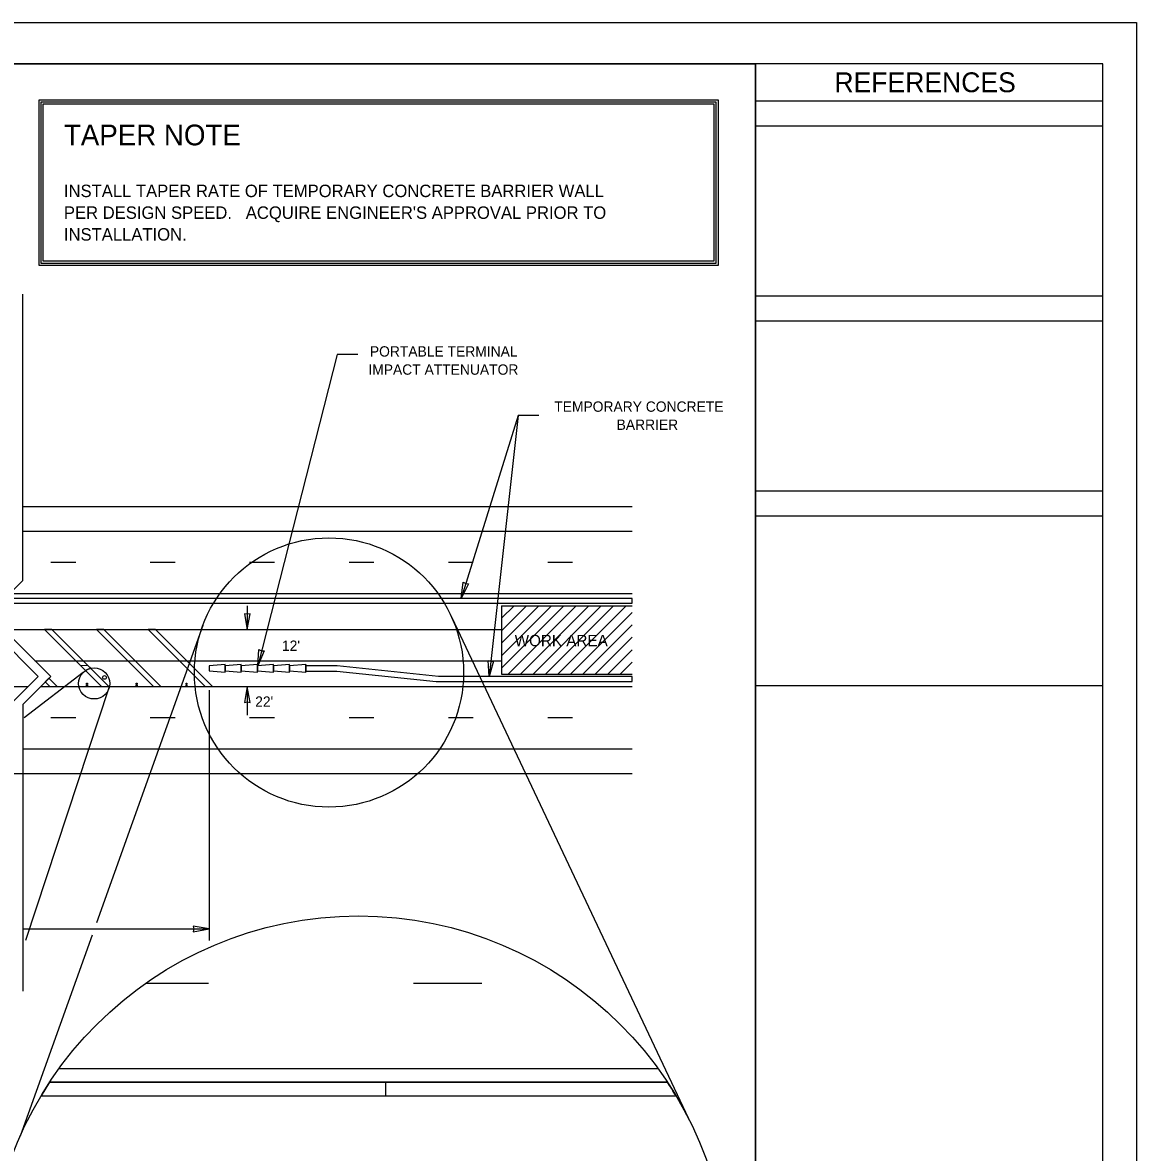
# Model space of a CAD drawing. Extents: x -2541 to -1265, y -5743 to -4928.
# Drawn here: x -1696.1 to -1265.8, y -5364.1 to -4927.7 of the extents above; entities that cross this region are included whole.
import ezdxf

# ---------------------------------------------------------------- set-up
doc = ezdxf.new("R2010")
doc.units = 0
for name, color, linetype in [('Level 42', 7, 'Continuous'), ('Level 45', 7, 'Continuous'), ('Level 46', 7, 'Continuous'), ('Level 47', 7, 'Continuous'), ('Level 48', 7, 'Continuous'), ('Level 49', 7, 'Continuous'), ('Level 50', 7, 'Continuous'), ('TR_WZ_TC_Edge Lines', 7, 'Continuous')]:
    doc.layers.add(name, color=color, linetype=linetype)

msp = doc.modelspace()

# ---------------------------------------------------------------- linework, layer by layer
at = {"layer": 'Level 42'}
for p, q in [((-1278.76, -4943.69), (-2472.96, -4943.66)), ((-1412.92, -5724.9), (-1412.92, -4943.73)), ((-1278.76, -5724.9), (-1278.76, -4943.69)), ((-1412.92, -4957.91), (-1278.91, -4957.91)), ((-1278.83, -4967.73), (-1412.92, -4967.73)), ((-1412.92, -5033.21), (-1278.91, -5033.21)), ((-1278.83, -5043.03), (-1412.92, -5043.03)), ((-1412.92, -5108.5), (-1278.91, -5108.5)), ((-1278.83, -5118.32), (-1412.92, -5118.32)), ((-1412.92, -5183.8), (-1278.76, -5183.8))]:
    msp.add_line(p, q, dxfattribs=at)
for points in [[(-2472.96, -4943.66), (-1412.92, -4943.66), (-1412.92, -5724.9), (-2472.96, -5724.9)], [(-1689.75, -4957.5), (-1427.42, -4957.5), (-1427.42, -5021.5), (-1689.75, -5021.5)], [(-1688.95, -4958.3), (-1428.22, -4958.3), (-1428.22, -5020.7), (-1688.95, -5020.7)], [(-1688.15, -4959.1), (-1429.02, -4959.1), (-1429.02, -5019.9), (-1688.15, -5019.9)]]:
    msp.add_lwpolyline(points, close=True, dxfattribs=at)
at = {"layer": 'Level 45'}
for p, q in [((-1701.04, -5148.16), (-1460.65, -5148.16)), ((-2451.65, -5184.16), (-1693.96, -5184.16)), ((-1689.15, -5184.16), (-1460.65, -5184.16)), ((-1671.38, -5183.2), (-1671.38, -5182.88)), ((-1671.38, -5182.88), (-1671.06, -5182.88)), ((-1671.06, -5183.2), (-1671.38, -5183.2)), ((-1671.38, -5183.84), (-1671.38, -5183.52)), ((-1671.38, -5183.52), (-1671.06, -5183.52)), ((-1671.06, -5183.84), (-1671.38, -5183.84)), ((-1671.06, -5182.88), (-1671.06, -5183.2)), ((-1671.06, -5183.52), (-1671.06, -5183.84)), ((-1652.18, -5183.2), (-1652.18, -5182.88)), ((-1652.18, -5182.88), (-1651.86, -5182.88)), ((-1651.86, -5183.2), (-1652.18, -5183.2)), ((-1652.18, -5183.84), (-1652.18, -5183.52)), ((-1652.18, -5183.52), (-1651.86, -5183.52)), ((-1651.86, -5183.84), (-1652.18, -5183.84)), ((-1651.86, -5182.88), (-1651.86, -5183.2)), ((-1651.86, -5183.52), (-1651.86, -5183.84)), ((-1632.98, -5183.2), (-1632.98, -5182.88)), ((-1632.98, -5182.88), (-1632.66, -5182.88)), ((-1632.66, -5183.2), (-1632.98, -5183.2)), ((-1632.98, -5183.84), (-1632.98, -5183.52)), ((-1632.98, -5183.52), (-1632.66, -5183.52)), ((-1632.66, -5183.84), (-1632.98, -5183.84)), ((-1632.66, -5182.88), (-1632.66, -5183.2)), ((-1632.66, -5183.52), (-1632.66, -5183.84)), ((-1682, -5331.68), (-1450.64, -5331.68))]:
    msp.add_line(p, q, dxfattribs=at)
at = {"layer": 'Level 46'}
for p, q in [((-1574.58, -5055.92), (-1605.29, -5176.11)), ((-1566.58, -5055.92), (-1574.58, -5055.92)), ((-1504.7, -5079.42), (-1526.67, -5150.08)), ((-1504.7, -5079.42), (-1515.86, -5180.32)), ((-1496.7, -5079.42), (-1504.7, -5079.42)), ((-1696.04, -5114.56), (-1460.65, -5114.56)), ((-1696.04, -5124.16), (-1460.65, -5124.16)), ((-1685.2, -5136.16), (-1675.6, -5136.16)), ((-1646.8, -5136.16), (-1637.2, -5136.16)), ((-1608.4, -5136.16), (-1598.8, -5136.16)), ((-1570, -5136.16), (-1560.4, -5136.16)), ((-1531.6, -5136.16), (-1522, -5136.16)), ((-1493.2, -5136.16), (-1483.6, -5136.16)), ((-1609.31, -5152.97), (-1609.31, -5162.16)), ((-1530.38, -5157.26), (-1438.83, -5350.98)), ((-1626.49, -5160.62), (-1667.56, -5275.39)), ((-1672.71, -5178.72), (-1695.47, -5196.18)), ((-1609.31, -5184.16), (-1609.31, -5195.16)), ((-1662.74, -5184.71), (-1694.97, -5282.26)), ((-1624.04, -5185.58), (-1624.04, -5282.21)), ((-1685.2, -5196.16), (-1675.6, -5196.16)), ((-1646.8, -5196.16), (-1637.2, -5196.16)), ((-1608.4, -5196.16), (-1598.8, -5196.16)), ((-1570, -5196.16), (-1560.4, -5196.16)), ((-1531.6, -5196.16), (-1522, -5196.16)), ((-1493.2, -5196.16), (-1483.6, -5196.16)), ((-1696.04, -5208.16), (-1460.65, -5208.16)), ((-1737.89, -5217.76), (-1460.65, -5217.76)), ((-1669.29, -5280.24), (-1697.04, -5357.77)), ((-1696.04, -5277.76), (-1624.04, -5277.76)), ((-1648.45, -5298.68), (-1624.23, -5298.68)), ((-1545.03, -5298.68), (-1518.63, -5298.68))]:
    msp.add_line(p, q, dxfattribs=at)
for centre, radius in [((-1577.74, -5178.72), 52), ((-1668.47, -5182.96), 6), ((-1566.32, -5415.75), 143)]:
    msp.add_circle(centre, radius, dxfattribs=at)
at = {"layer": 'Level 47'}
for p, q in [((-1506.22, -5153), (-1511.03, -5157.8)), ((-1501.41, -5153), (-1511.03, -5162.61)), ((-1496.61, -5153), (-1511.03, -5167.42)), ((-1491.8, -5153), (-1511.03, -5172.23)), ((-1486.99, -5153), (-1511.03, -5177.04)), ((-1511.03, -5153), (-1511.03, -5179.32)), ((-1511.03, -5153), (-1460.65, -5153)), ((-1482.18, -5153), (-1508.5, -5179.32)), ((-1477.37, -5153), (-1503.69, -5179.32)), ((-1472.56, -5153), (-1498.88, -5179.32)), ((-1467.76, -5153), (-1494.08, -5179.32)), ((-1462.95, -5153), (-1489.27, -5179.32)), ((-1460.65, -5155.5), (-1484.46, -5179.32)), ((-1460.65, -5160.31), (-1479.65, -5179.32)), ((-1460.65, -5165.12), (-1474.84, -5179.32)), ((-1460.65, -5169.93), (-1470.03, -5179.32)), ((-1460.65, -5174.74), (-1465.23, -5179.32)), ((-1511.03, -5179.32), (-1460.65, -5179.32))]:
    msp.add_line(p, q, dxfattribs=at)
at = {"layer": 'Level 48'}
for p, q in [((-1704.88, -5152), (-1460.65, -5152)), ((-1460.65, -5150.08), (-1702.96, -5150.08)), ((-1460.65, -5152), (-1460.65, -5150.08)), ((-1586.74, -5178.56), (-1586.74, -5175.68)), ((-1586.74, -5175.68), (-1586.74, -5178.56)), ((-1574.64, -5176.16), (-1586.74, -5176.16)), ((-1586.74, -5176.16), (-1586.74, -5178.16)), ((-1586.74, -5178.16), (-1574.74, -5178.16)), ((-1574.74, -5178.16), (-1536.34, -5182.24)), ((-1535.48, -5180.32), (-1574.64, -5176.16)), ((-1536.34, -5182.24), (-1460.65, -5182.24)), ((-1460.65, -5180.32), (-1535.48, -5180.32)), ((-1460.65, -5182.24), (-1460.65, -5180.32)), ((-1685.66, -5336.96), (-1688.98, -5342.24)), ((-1685.66, -5336.96), (-1446.98, -5336.96)), ((-1446.98, -5336.96), (-1685.66, -5336.96)), ((-1555.88, -5336.96), (-1555.88, -5342.24)), ((-1688.98, -5342.24), (-1443.66, -5342.24)), ((-1688.98, -5342.24), (-1443.66, -5342.24))]:
    msp.add_line(p, q, dxfattribs=at)
msp.add_arc((-1566.32, -5415.75), 143, 30.9326, 33.4324, dxfattribs=at)
at = {"layer": 'Level 49'}
for p, q in [((-1526.67, -5150.08), (-1525.88, -5143.89)), ((-1523.81, -5144.53), (-1526.67, -5150.08)), ((-1525.88, -5143.89), (-1524.9, -5144.39)), ((-1524.9, -5144.39), (-1523.81, -5144.53)), ((-1609.31, -5156.2), (-1610.39, -5156.01)), ((-1610.39, -5156.01), (-1609.31, -5162.16)), ((-1609.31, -5162.16), (-1608.22, -5156.01)), ((-1608.22, -5156.01), (-1609.31, -5156.2)), ((-1605.29, -5176.11), (-1604.82, -5169.89)), ((-1602.72, -5170.42), (-1605.29, -5176.11)), ((-1604.82, -5169.89), (-1603.82, -5170.34)), ((-1603.82, -5170.34), (-1602.72, -5170.42)), ((-1515.86, -5180.32), (-1516.26, -5174.09)), ((-1516.26, -5174.09), (-1515.21, -5174.4)), ((-1514.11, -5174.33), (-1515.86, -5180.32)), ((-1515.21, -5174.4), (-1514.11, -5174.33)), ((-1609.31, -5184.16), (-1610.39, -5190.3)), ((-1608.22, -5190.3), (-1609.31, -5184.16)), ((-1610.39, -5190.3), (-1609.31, -5190.11)), ((-1609.31, -5190.11), (-1608.22, -5190.3)), ((-1624.04, -5277.76), (-1630.19, -5276.67)), ((-1630.19, -5276.67), (-1630, -5277.76)), ((-1630, -5277.76), (-1630.19, -5278.84)), ((-1630.19, -5278.84), (-1624.04, -5277.76))]:
    msp.add_line(p, q, dxfattribs=at)
at = {"layer": 'Level 50'}
for p, q in [((-1696.04, -5143.15), (-1696.04, -5032.65)), ((-1709.22, -5156.33), (-1696.04, -5143.15)), ((-1690.08, -5180.27), (-1714.02, -5156.33)), ((-1685.27, -5180.27), (-1709.22, -5156.33)), ((-1617.82, -5175.68), (-1624.04, -5176.16)), ((-1624.04, -5176.16), (-1624.04, -5178.08)), ((-1624.04, -5178.08), (-1617.82, -5178.56)), ((-1617.82, -5178.56), (-1617.82, -5175.68)), ((-1611.61, -5175.68), (-1617.82, -5176.16)), ((-1617.82, -5176.16), (-1617.82, -5178.08)), ((-1617.82, -5178.08), (-1611.61, -5178.56)), ((-1611.61, -5178.56), (-1611.61, -5175.68)), ((-1605.39, -5175.68), (-1611.61, -5176.16)), ((-1611.61, -5176.16), (-1611.61, -5178.08)), ((-1611.61, -5177.12), (-1611.61, -5177.12)), ((-1611.61, -5178.08), (-1605.39, -5178.56)), ((-1605.39, -5178.56), (-1605.39, -5175.68)), ((-1599.18, -5175.68), (-1605.39, -5176.16)), ((-1605.39, -5176.16), (-1605.39, -5178.08)), ((-1605.39, -5178.08), (-1599.18, -5178.56)), ((-1599.18, -5178.56), (-1599.18, -5175.68)), ((-1592.96, -5175.68), (-1599.18, -5176.16)), ((-1599.18, -5176.16), (-1599.18, -5178.08)), ((-1599.18, -5178.08), (-1592.96, -5178.56)), ((-1592.96, -5178.56), (-1592.96, -5175.68)), ((-1586.74, -5175.68), (-1592.96, -5176.16)), ((-1592.96, -5176.16), (-1592.96, -5178.08)), ((-1592.96, -5178.08), (-1586.74, -5178.56)), ((-1586.74, -5178.56), (-1586.74, -5175.68)), ((-1699.44, -5189.63), (-1690.08, -5180.27)), ((-1696.04, -5191.04), (-1685.27, -5180.27)), ((-1696.04, -5191.04), (-1696.04, -5301.83))]:
    msp.add_line(p, q, dxfattribs=at)
msp.add_lwpolyline([(-2541.13, -4927.7), (-1265.77, -4927.7), (-1265.77, -5742.8), (-2541.13, -5742.8)], close=True, dxfattribs=at)
msp.add_circle((-1664.47, -5180.62), 0.72, dxfattribs=at)
at = {"layer": 'TR_WZ_TC_Edge Lines'}
for p, q in [((-1703.39, -5162.16), (-1511.03, -5162.16)), ((-1684.76, -5162.16), (-1687.59, -5162.16)), ((-1687.59, -5162.16), (-1665.59, -5184.16)), ((-1662.76, -5184.16), (-1684.76, -5162.16)), ((-1664.76, -5162.16), (-1667.59, -5162.16)), ((-1667.59, -5162.16), (-1645.59, -5184.16)), ((-1642.76, -5184.16), (-1664.76, -5162.16)), ((-1644.76, -5162.16), (-1647.59, -5162.16)), ((-1647.59, -5162.16), (-1625.59, -5184.16)), ((-1622.76, -5184.16), (-1644.76, -5162.16)), ((-1625.63, -5162.16), (-1624.04, -5162.16)), ((-1665.59, -5184.16), (-1685.12, -5164.63)), ((-1662.76, -5184.16), (-1682.4, -5164.52)), ((-1645.59, -5184.16), (-1665.92, -5163.83)), ((-1642.76, -5184.16), (-1663.2, -5163.72)), ((-1625.59, -5184.16), (-1646.72, -5163.03)), ((-1622.76, -5184.16), (-1644, -5162.92)), ((-1691.39, -5174.16), (-1511.03, -5174.16)), ((-1625.38, -5174.16), (-1511.03, -5174.16)), ((-1670.87, -5176.05), (-1673.59, -5176.16)), ((-1673.59, -5176.16), (-1671.79, -5177.96)), ((-1669.81, -5177.11), (-1670.87, -5176.05)), ((-1685.93, -5180.94), (-1687.35, -5182.35)), ((-1685.54, -5184.16), (-1687.35, -5182.35)), ((-1687.35, -5182.35), (-1685.54, -5184.16)), ((-1682.72, -5184.16), (-1685.93, -5180.94)), ((-1682.72, -5184.16), (-1685.93, -5180.94)), ((-1685.54, -5184.16), (-1682.72, -5184.16)), ((-1665.59, -5184.16), (-1662.76, -5184.16)), ((-1645.59, -5184.16), (-1642.76, -5184.16)), ((-1625.59, -5184.16), (-1622.76, -5184.16))]:
    msp.add_line(p, q, dxfattribs=at)
msp.add_arc((-1668.47, -5182.96), 6, 102.8853, 123.5634, dxfattribs=at)

# ---------------------------------------------------------------- texts
at = {"layer": 'Level 42'}
for s, height, p in [('REFERENCES', 7.667, (-1382.45, -4954.59)), ('TAPER NOTE', 8, (-1680.15, -4975.1)), ('INSTALL TAPER RATE OF TEMPORARY CONCRETE BARRIER WALL', 4.8, (-1680.15, -4995.1)), ("PER DESIGN SPEED.   ACQUIRE ENGINEER'S APPROVAL PRIOR TO", 4.8, (-1680.15, -5003.5)), ('INSTALLATION.', 4.8, (-1680.15, -5011.9)), ('PORTABLE TERMINAL', 4, (-1561.94, -5056.71)), ('IMPACT ATTENUATOR', 4, (-1562.51, -5063.71)), ('TEMPORARY CONCRETE', 4, (-1490.7, -5078.02)), ('BARRIER', 4, (-1466.61, -5085.02)), ("12'", 4, (-1595.91, -5170.38)), ("22'", 4, (-1606.26, -5191.98))]:
    msp.add_text(s, height=height, dxfattribs=at).set_placement(p)
at = {"layer": 'TR_WZ_TC_Edge Lines'}
msp.add_text('WORK AREA', height=4.4, dxfattribs=at).set_placement((-1505.99, -5168.58))

doc.saveas('drawing.dxf')
